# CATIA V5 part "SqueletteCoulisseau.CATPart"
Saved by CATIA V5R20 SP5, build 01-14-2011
Part number: SqueletteCoulisseau
Publications: "Droite.1", "Plan.2", "Droite.2"
Bounding box of the stored display mesh (mm): x 0 to 0, y 210 to 350, z -20 to 80
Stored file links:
  F:\IAO_bmadec\bmadecf\SqueletteCoulisseau.CATPart
  F:\IAO_bmadec\bmadecf\squelette.CATProduct
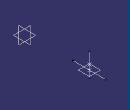
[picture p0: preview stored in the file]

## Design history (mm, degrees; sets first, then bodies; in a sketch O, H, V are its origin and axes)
Set1
  Plane1: linked copy from another document
  Point1: linked copy from another document
  Point2: linked copy from another document
  Plane2: linked copy from another document
Set2
  Line1: type Normal, RefPoint Point1, RefSkin Plane1, Start -50, End 50
  Plane3: type OffsetPt, RefPlane Plane1, RefPoint Point2
  Line2: type Normal, RefPoint Point2, RefSkin Plane2, Start -70, End 70
Body1 (main body)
